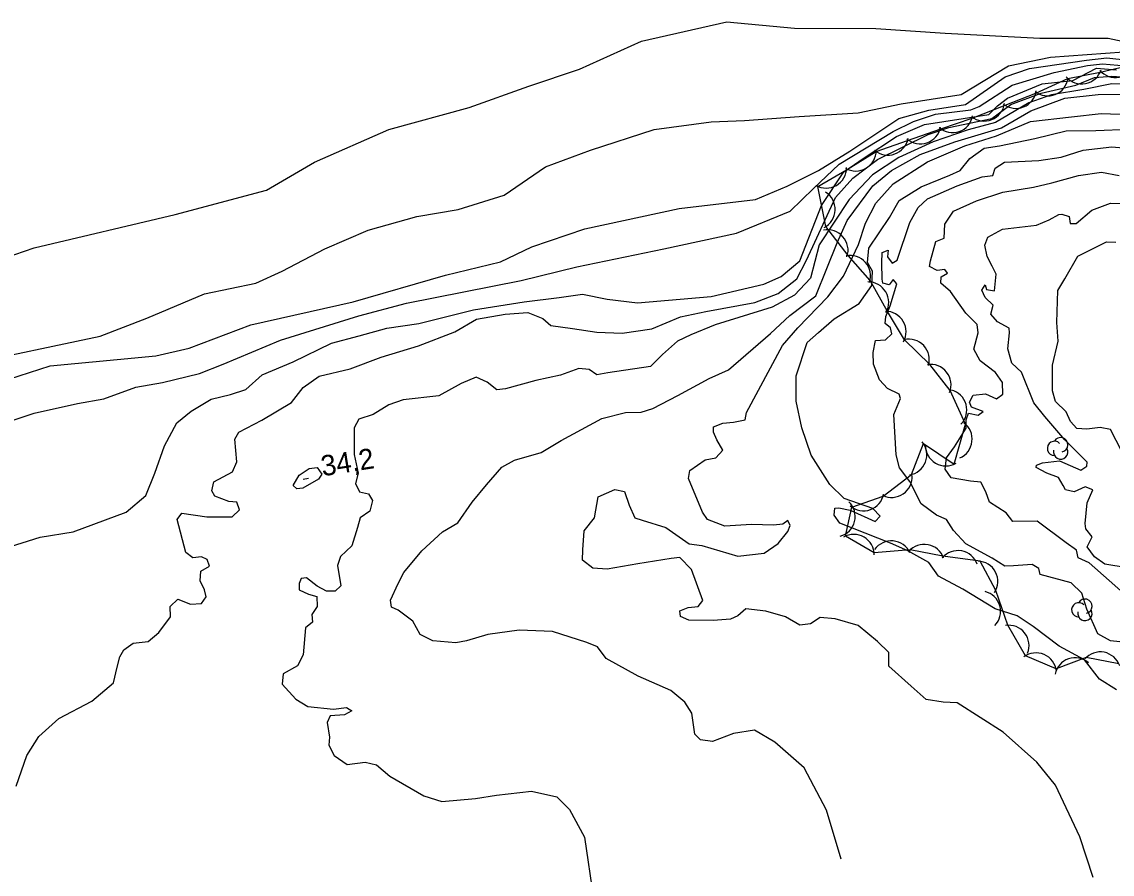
# Model space of a CAD drawing. Extents: x 646142 to 649934, y 5874075 to 5876351.
# Drawn here: x 648669.3 to 648828.8, y 5874823.8 to 5874948.5 of the extents above; entities that cross this region are included whole.
import ezdxf

# ---------------------------------------------------------------- set-up
doc = ezdxf.new("R2010")
doc.units = 0
for name, color, linetype in [('Niveau 1', 7, 'Continuous'), ('Niveau 2', 7, 'Continuous'), ('Niveau 3', 7, 'Continuous'), ('Niveau 44', 7, 'Continuous')]:
    doc.layers.add(name, color=color, linetype=linetype)

msp = doc.modelspace()

# ---------------------------------------------------------------- linework, layer by layer
at = {"layer": 'Niveau 1'}
for points in [[(648664.99, 5874870.88), (648672.04, 5874873.1), (648676.83, 5874873.89), (648684.62, 5874876.77), (648687.46, 5874879.19), (648688.81, 5874882.48), (648690.19, 5874886.47), (648692, 5874889.81), (648694.11, 5874891.56), (648697.04, 5874893.3), (648699.86, 5874893.97), (648702.1, 5874894.7), (648704.51, 5874896.84), (648709.04, 5874898.75), (648714.63, 5874901.49), (648718.69, 5874902.55), (648722.72, 5874903.71), (648727.4, 5874904.37), (648735.41, 5874906.35), (648742.8, 5874907.56), (648747.95, 5874908.16), (648751.37, 5874908.67), (648754.94, 5874907.93), (648759.41, 5874907.4), (648770.2, 5874908.31), (648777.87, 5874910.13), (648780.4, 5874911.24), (648783.14, 5874913.53), (648786.34, 5874921.66), (648789.57, 5874926.56), (648792.57, 5874928.64), (648797.29, 5874931.74), (648801.37, 5874933.49), (648807.06, 5874934.38), (648810.81, 5874934.94), (648812.05, 5874936.24), (648813.54, 5874937.34), (648818.61, 5874939.43), (648823.07, 5874939.95), (648826.56, 5874941.75), (648829.48, 5874941.51)], [(648789.02, 5874875.13), (648788.19, 5874876.3), (648788.29, 5874877.35), (648788.86, 5874877.41), (648790.51, 5874877.03), (648794.16, 5874875.39), (648794.88, 5874876.16), (648793.82, 5874877.3), (648789.62, 5874878.77), (648787.53, 5874880.82), (648784.82, 5874885.11), (648783.43, 5874889.09), (648782.61, 5874893.02), (648782.62, 5874896.7), (648784.22, 5874901.6), (648785.88, 5874903.06), (648788.18, 5874905.05), (648791.81, 5874907.31), (648793.68, 5874909.95), (648793.78, 5874912.03), (648793.04, 5874913.32), (648793.25, 5874915.41), (648796.28, 5874919.9), (648797.7, 5874922.37), (648800.91, 5874924.35), (648805.07, 5874926.1), (648806.61, 5874926.74), (648808, 5874928.51), (648810.12, 5874930.02), (648812.37, 5874930.39), (648817.53, 5874931.45), (648822.11, 5874932.56), (648826.47, 5874932.61), (648826.47, 5874932.61), (648831.27, 5874932.82)], [(648829.46, 5874850.75), (648826.97, 5874852.3), (648824.79, 5874855.15), (648821.1, 5874857.14), (648817.3, 5874860.03), (648814.92, 5874861.59), (648811.7, 5874862.6), (648806.98, 5874865.5), (648803.41, 5874867.38), (648802.02, 5874869.4), (648798.94, 5874871.11), (648796.39, 5874872.2), (648789.02, 5874875.13)]]:
    msp.add_lwpolyline(points, dxfattribs=at)
at = {"layer": 'Niveau 2'}
for points in [[(648649.86, 5874908.14), (648671.16, 5874915.44), (648691.75, 5874920.32), (648705.15, 5874923.91), (648712.14, 5874927.99), (648723.01, 5874932.76), (648734.77, 5874935.99), (648743.5, 5874939.1), (648750.9, 5874941.59), (648759.98, 5874945.68), (648772.47, 5874948.53), (648782.38, 5874947.58), (648794.28, 5874947.57), (648804.39, 5874946.88)], [(648804.39, 5874946.88), (648818.24, 5874946.15), (648828.26, 5874946.15), (648845.02, 5874942.51), (648856.18, 5874939.85), (648884.49, 5874933.12), (648906.85, 5874927.33), (648926.66, 5874923.35), (648935.29, 5874921.33), (648949.8, 5874920.69), (648964.39, 5874919.36), (648976.84, 5874914.53), (648990.17, 5874906.3), (649000.31, 5874901.42), (649016.05, 5874896.28), (649031.58, 5874894.83), (649049.16, 5874893.62), (649079, 5874896.65)], [(648660.88, 5874898.32), (648680.8, 5874902.5), (648687.6, 5874905.16), (648696.04, 5874908.7), (648703.55, 5874910.28), (648707.43, 5874912.01), (648713.68, 5874915.3), (648720, 5874918.02), (648727.11, 5874920.01), (648733.16, 5874921.06), (648739.91, 5874923.13), (648745.93, 5874927.32), (648752.52, 5874929.72), (648761.82, 5874932.78), (648770.2, 5874933.87), (648775.06, 5874934.08), (648783.03, 5874934.66), (648791.7, 5874935.2), (648797.95, 5874936.51), (648806.75, 5874937.88), (648813.69, 5874942.07), (648819.82, 5874943.36), (648830.55, 5874944.14)], [(648667.44, 5874896.2), (648673.5, 5874898.19), (648683.29, 5874899.09), (648688.94, 5874899.63), (648693.81, 5874900.78), (648702.84, 5874904.16), (648717.81, 5874907.53), (648731.31, 5874911.43), (648739.34, 5874913.41), (648743.96, 5874915.58), (648751.68, 5874918.22), (648765.51, 5874921.22), (648776.64, 5874922.52), (648781.29, 5874924.46), (648785.9, 5874926.74), (648790.44, 5874929.59), (648797.65, 5874934.38), (648802.04, 5874935.59), (648807.4, 5874936.44), (648813.19, 5874940.48), (648816.76, 5874941.71), (648825.1, 5874942.91), (648828.08, 5874943.26), (648834.32, 5874942.59)], [(648796.81, 5874932.45), (648799.76, 5874933.95), (648803, 5874935.03), (648808.15, 5874935.62), (648809.37, 5874936.11), (648814.22, 5874939.23), (648820.37, 5874941.1), (648825.24, 5874942.13), (648827.41, 5874942.39), (648830.81, 5874942.09)], [(648689.39, 5874859.16), (648691.09, 5874861.45), (648691.02, 5874862.95), (648692.17, 5874864.01), (648694, 5874863.29), (648695.61, 5874863.37), (648696.3, 5874864.37), (648696.07, 5874865.39), (648695.44, 5874866.71), (648695.51, 5874868.11), (648696.81, 5874868.84), (648696.46, 5874869.84), (648695.61, 5874870.2), (648694.35, 5874870.05), (648693.32, 5874870.86), (648692.05, 5874875.69), (648692.75, 5874876.59), (648696.41, 5874876.09), (648700.12, 5874876.06), (648701.16, 5874877.11), (648700.79, 5874878.22), (648699.62, 5874878.32), (648697.55, 5874879.12), (648697.12, 5874879.88), (648697.42, 5874881.19), (648700.14, 5874882.66), (648700.78, 5874884.13), (648700.5, 5874887.45), (648701.07, 5874888.45), (648704.45, 5874890.23), (648708.78, 5874892.82), (648710.49, 5874894.99), (648712.84, 5874896.65), (648717.35, 5874897.75), (648721.9, 5874899.44), (648721.9, 5874899.44), (648727.37, 5874901.12), (648732.69, 5874903.13), (648735.83, 5874905), (648740.03, 5874905.72), (648743.36, 5874905.99), (648745.55, 5874905.09), (648746.71, 5874904.07), (648749.89, 5874903.63), (648753.43, 5874903.11), (648757.15, 5874902.97), (648761.48, 5874903.59), (648765.67, 5874905.35), (648769.4, 5874906.13), (648776.54, 5874907.43), (648779.96, 5874908.75), (648782.71, 5874910.92), (648784.12, 5874913.63), (648788.34, 5874922.8), (648790.9, 5874925.64), (648794.5, 5874928.37), (648801.93, 5874932.01), (648804.93, 5874933.06), (648811.25, 5874934.37), (648814.01, 5874936.43), (648818.43, 5874938.1), (648823.5, 5874939.26), (648826.25, 5874940.39), (648828.78, 5874940.57), (648835.07, 5874940.15)], [(648832.94, 5874939.35), (648828.77, 5874939.44), (648824.71, 5874938.63), (648819.95, 5874937.84), (648816.63, 5874936.65), (648811.78, 5874933.78), (648807.75, 5874932.73), (648802.65, 5874930.98), (648797.61, 5874928.66), (648793.76, 5874926.14), (648790.38, 5874922.51), (648785.98, 5874915.88), (648784.72, 5874910.99), (648782.36, 5874908.52), (648779.1, 5874906.76), (648770.75, 5874904.17)], [(648789.18, 5874825.98), (648787.05, 5874833.13), (648783.77, 5874839.32), (648779.5, 5874843.1), (648776.52, 5874844.83), (648773.46, 5874844.35), (648770.37, 5874843.18), (648768.6, 5874843.44), (648767.81, 5874844.27), (648767.33, 5874847.33), (648766.32, 5874848.95), (648764.27, 5874850.67), (648759.51, 5874852.77), (648754.82, 5874855.34), (648753.57, 5874857.04), (648751.99, 5874857.66), (648746.95, 5874859.27), (648742.07, 5874859.5), (648737.53, 5874858.86), (648734.4, 5874857.92), (648732.82, 5874857.61), (648729.44, 5874857.91), (648727.59, 5874858.85), (648726.55, 5874860.81), (648724.39, 5874862.4), (648723.41, 5874862.87), (648723.29, 5874863.89), (648724.38, 5874866.33), (648725.23, 5874867.93), (648727.85, 5874871.12), (648730.87, 5874873.9), (648733.14, 5874875.2), (648735.2, 5874878.21), (648737.32, 5874880.77), (648739.56, 5874883.34), (648741.4, 5874884.36), (648745.3, 5874885.51), (648748.21, 5874887.23), (648754.17, 5874890.47), (648757.65, 5874891.33), (648759.95, 5874891.37), (648761.62, 5874891.91), (648765.31, 5874893.84), (648769.86, 5874896.34), (648772.71, 5874897.59), (648778.88, 5874902.92), (648781.68, 5874905.56), (648785.49, 5874908.42), (648787.09, 5874912.41), (648788.6, 5874916.17), (648790.05, 5874919.45), (648793.82, 5874924.5), (648796.55, 5874926.78), (648800.76, 5874929.11), (648805.84, 5874930.97), (648812.63, 5874933.03), (648816.95, 5874935.49), (648821.91, 5874937.33), (648826.8, 5874937.9), (648831.29, 5874937.96)], [(648773.45, 5874889.95), (648775.14, 5874890.26), (648775.14, 5874890.26), (648775.36, 5874891.33), (648780.63, 5874901.16), (648782.86, 5874903.72), (648787.26, 5874908.26), (648789.55, 5874911.29), (648791.75, 5874915.92), (648792.76, 5874919.04), (648794.25, 5874921.97), (648796.79, 5874924.8), (648801.81, 5874928.03), (648807.29, 5874930.39), (648811.94, 5874931.86), (648816.88, 5874933.93), (648822.89, 5874934.63), (648827.21, 5874935.13), (648835.53, 5874934.83)], [(648666.88, 5874889.81), (648671.13, 5874891.23), (648677.47, 5874892.67), (648681.35, 5874893.35), (648686.03, 5874895.06), (648689.9, 5874895.74), (648695.33, 5874897.07), (648698.77, 5874898.4), (648707.19, 5874901.94), (648718.62, 5874905.47), (648725.61, 5874907.33), (648742.4, 5874910.68), (648750.53, 5874912.67), (648763.23, 5874915.31), (648773.87, 5874917.6), (648781.72, 5874920.83), (648785.16, 5874924.13), (648788.91, 5874927.7), (648796.81, 5874932.45)], [(648795.19, 5874914.75), (648796.07, 5874915.08), (648795.95, 5874914.15), (648796.64, 5874913.2), (648797.39, 5874913.63), (648799.25, 5874919.13), (648800.48, 5874921.33), (648801.82, 5874922.64), (648806.18, 5874924.52), (648809.81, 5874925.86), (648811.39, 5874926.05), (648811.72, 5874927.12), (648813.11, 5874927.97), (648818.13, 5874928.21), (648821.4, 5874928.7), (648824.6, 5874929.76), (648828.79, 5874930.25), (648834.35, 5874929.75)], [(648802.12, 5874912.71), (648802.25, 5874913.52), (648803.06, 5874916.37), (648804.26, 5874916.85), (648804.35, 5874918.92), (648805.62, 5874920.79), (648808.98, 5874922.33), (648812.84, 5874923.58), (648817.34, 5874924.33), (648820.01, 5874924.98), (648823.89, 5874926.01), (648827.27, 5874926.52), (648829.85, 5874926.01)], [(648810.66, 5874917.03), (648812.81, 5874918.2), (648817.77, 5874918.77), (648819.62, 5874919.56), (648821.02, 5874920.3), (648821.47, 5874920.35), (648822.54, 5874920.02), (648822.67, 5874919), (648823.58, 5874918.99), (648825.86, 5874920.97), (648828.6, 5874921.98), (648830.09, 5874921.92)], [(648831.04, 5874868.6), (648827.77, 5874869.14), (648826.27, 5874870.22), (648825.17, 5874871.7), (648825.91, 5874873.16), (648824.97, 5874874.31), (648824.88, 5874875.1), (648825.2, 5874878.11), (648826, 5874880.03), (648824.91, 5874880.48), (648823.29, 5874879.72), (648821.99, 5874880.02), (648821.69, 5874880.67), (648820.97, 5874881.85), (648819.3, 5874882.46), (648817.71, 5874883.3), (648817.78, 5874883.65), (648818.65, 5874883.98), (648821.14, 5874884.27), (648824.27, 5874882.92), (648825.12, 5874883.48), (648825.17, 5874884.06), (648821.91, 5874887.34), (648818.98, 5874890.77), (648817.37, 5874892.76), (648815.57, 5874897.24), (648814.15, 5874898.56), (648813.55, 5874900.67), (648813.84, 5874902.99), (648813.76, 5874903.67), (648812.05, 5874904.61), (648811.11, 5874905.76), (648811.41, 5874907.05), (648810.24, 5874908.17), (648809.77, 5874909.26), (648810.25, 5874910.01), (648810.44, 5874909.34), (648811.61, 5874909.14), (648811.89, 5874911.57), (648811.29, 5874912.76), (648810.55, 5874914.16), (648810.23, 5874915.84), (648810.66, 5874917.03)], [(648830.23, 5874885.63), (648828.58, 5874888.87), (648827.06, 5874889.15), (648825.14, 5874888.92), (648823.65, 5874888.98), (648822.73, 5874890.01), (648822.1, 5874891.42), (648820.54, 5874892.96), (648820.13, 5874894.51), (648820.13, 5874898.28), (648820.96, 5874901.8), (648820.75, 5874904.52), (648820.87, 5874909.21), (648821.92, 5874910.93), (648823.8, 5874914.24), (648828, 5874916.32), (648829.38, 5874916.26)], [(648832.75, 5874857.48), (648828.57, 5874857.91), (648826.72, 5874858.96), (648825.14, 5874862.56), (648824.4, 5874864.89), (648822.83, 5874866.43), (648818.32, 5874867.63), (648818.1, 5874868.52), (648817.11, 5874869.09), (648814.38, 5874868.89), (648813.12, 5874868.85), (648811.26, 5874870.02), (648807.45, 5874872.1), (648805.61, 5874874.06), (648804.61, 5874875.67), (648803.15, 5874876.3), (648800.88, 5874877.99), (648799.23, 5874881.24), (648797.72, 5874883.25), (648797.26, 5874885.15), (648796.89, 5874891.07), (648797.88, 5874893.37), (648797.69, 5874894.04), (648795.98, 5874894.87), (648794.8, 5874896.11), (648793.94, 5874898.42), (648793.85, 5874900.13), (648794.21, 5874901.9), (648795.7, 5874901.96), (648796.62, 5874902.87), (648796.4, 5874903.76), (648795.64, 5874904.36), (648795.74, 5874905.4), (648796.36, 5874906.97), (648797.35, 5874910.18), (648796.81, 5874910.81), (648796.22, 5874910.05), (648795.27, 5874910.28), (648795.2, 5874910.85), (648795.14, 5874913.25), (648795.19, 5874914.75)], [(648830.47, 5874864.89), (648825.46, 5874869.35), (648823.88, 5874870.09), (648823.63, 5874871.2), (648822.13, 5874872.29), (648817.85, 5874875.46), (648814.3, 5874875.39), (648813.35, 5874876.65), (648810.87, 5874878.2), (648810.34, 5874879.74), (648809.6, 5874881.14), (648808.09, 5874881.31), (648805.28, 5874881.79), (648804.43, 5874883.06), (648804.58, 5874884.69), (648805.76, 5874886.31), (648807.5, 5874889.04), (648807.46, 5874890.29), (648807.8, 5874891.25), (648809.22, 5874890.96), (648809.95, 5874891.5), (648808.27, 5874892.11), (648807.95, 5874892.87), (648808.52, 5874893.86), (648810.33, 5874894.07), (648811.91, 5874893.33), (648812.86, 5874894.02), (648812.77, 5874895.73), (648811.78, 5874897.22), (648809.52, 5874898.9), (648808.62, 5874900.63), (648809.25, 5874902.99), (648809.1, 5874904.24), (648807.42, 5874905.87), (648805.2, 5874909.05), (648803.79, 5874910.27), (648803.8, 5874911.18), (648804.76, 5874911.75), (648804.35, 5874912.28), (648803.22, 5874912.15), (648802.12, 5874912.71)], [(648770.75, 5874904.17), (648767.22, 5874902.72), (648767.22, 5874902.72), (648765.25, 5874901.79), (648763.06, 5874899.81), (648761.3, 5874898.1), (648755.06, 5874897.14), (648753.47, 5874896.84), (648752.34, 5874897.63), (648750.81, 5874897.8), (648748.16, 5874896.8), (648744.55, 5874896.03), (648740.07, 5874894.81), (648738.81, 5874894.67), (648737.41, 5874895.78), (648735.82, 5874896.52), (648733.62, 5874895.57), (648730.36, 5874893.8), (648725.11, 5874893.19), (648723, 5874892.48), (648720.74, 5874891.06), (648718.62, 5874890.35), (648717.96, 5874889.12), (648717.97, 5874885.19), (648718.53, 5874882.48), (648718.13, 5874880.93), (648718.74, 5874879.73), (648720.05, 5874879.42), (648720.63, 5874878.44), (648720.24, 5874876.89), (648718.85, 5874875.92), (648718.44, 5874874.49), (648717.6, 5874871.85), (648715.94, 5874870.26), (648715.52, 5874868.94), (648715.99, 5874865.99), (648715.16, 5874865.2), (648713.89, 5874865.17), (648712.52, 5874865.93), (648710.99, 5874867.14), (648710.19, 5874867.05), (648709.93, 5874866.32), (648709.92, 5874865.4), (648711.28, 5874864.75), (648712.47, 5874864.42), (648712.54, 5874862.93), (648711.74, 5874861.79), (648711.88, 5874860.65), (648710.82, 5874859.83), (648710.49, 5874855.86), (648709.64, 5874854.26), (648707.58, 5874853.09), (648707.41, 5874851.57), (648709.41, 5874849.37), (648711.16, 5874848.31), (648714.91, 5874847.93), (648716.85, 5874848.16), (648717.6, 5874847.67), (648716.52, 5874847.08), (648714.45, 5874846.95), (648713.99, 5874845.98), (648714.36, 5874843.82), (648714.27, 5874842.65), (648715.03, 5874841.12), (648716.92, 5874839.84)], [(648806.18, 5874848.84), (648804.09, 5874848.94), (648801.62, 5874849.34), (648799.43, 5874851.27), (648796.19, 5874854.24), (648796.18, 5874856.2), (648794.49, 5874857.84), (648791.67, 5874860.16), (648788.33, 5874861.16), (648786.11, 5874861.36), (648784.73, 5874860.39), (648783.14, 5874860.2), (648781.03, 5874861.45), (648778.16, 5874862.27), (648775.24, 5874862.62), (648774.1, 5874861.57), (648773, 5874861.09), (648770.49, 5874860.91), (648766.91, 5874860.96), (648765.69, 5874861.51), (648765.59, 5874862.3), (648766.8, 5874862.79), (648768.28, 5874862.96), (648768.98, 5874863.85), (648767.29, 5874868.38), (648765.58, 5874870.14), (648764.32, 5874869.99), (648759.46, 5874869.19), (648754.94, 5874868.43), (648752.85, 5874868.54), (648751.33, 5874869.74), (648751.38, 5874871.24), (648751.62, 5874874.04), (648753.12, 5874875.94), (648753.67, 5874879), (648756.08, 5874880.09), (648757.5, 5874879.8), (648758.2, 5874877.8), (648759, 5874875.94), (648760.08, 5874875.6), (648763.55, 5874874.51), (648766.95, 5874872.14), (648768.82, 5874871.9), (648774.08, 5874870.32), (648777.95, 5874870.77), (648779.97, 5874872.16), (648781.37, 5874873.94), (648781.73, 5874874.79), (648781.41, 5874875.56), (648780.67, 5874875.01), (648779.3, 5874874.85), (648776.06, 5874874.93), (648772.17, 5874874.71), (648769.63, 5874875.68), (648768.93, 5874876.75), (648766.84, 5874881.69), (648767.04, 5874882.87), (648769.28, 5874884.4), (648770.86, 5874884.7), (648771.87, 5874885.85), (648771, 5874887.36), (648770.52, 5874888.46), (648770.54, 5874889.27), (648771.86, 5874889.77), (648773.45, 5874889.95)], [(648709.89, 5874882.17), (648711.39, 5874883.15), (648712.53, 5874883.29), (648713.22, 5874882.33), (648712.74, 5874881.58), (648710.46, 5874880.27), (648709.55, 5874880.16), (648709.02, 5874880.68), (648709.89, 5874882.17)], [(648668.53, 5874836.67), (648670.08, 5874841.14), (648671.84, 5874843.9), (648674.77, 5874846.56), (648679.57, 5874849.09), (648682.73, 5874851.78), (648683.27, 5874854.05), (648683.67, 5874855.6), (648684.24, 5874856.59), (648685.64, 5874857.57), (648687.81, 5874857.82), (648689.39, 5874859.16)], [(648826.08, 5874823.27), (648824.09, 5874829.26), (648820.53, 5874836.8), (648817.82, 5874840.17), (648812.91, 5874844.55), (648806.18, 5874848.84)], [(648716.92, 5874839.84), (648719.55, 5874840.15), (648721.22, 5874839.76), (648723.15, 5874838.14), (648728.12, 5874835.25), (648730.77, 5874834.4), (648735.69, 5874834.86), (648738.76, 5874835.34), (648743.9, 5874835.94), (648747.59, 5874835.1), (648749.43, 5874833.23), (648751.65, 5874829.21), (648752.96, 5874820.22), (648753.84, 5874810.02), (648753.02, 5874797.54), (648747.53, 5874782.54), (648742.53, 5874772.11), (648739.6, 5874765.62), (648733.51, 5874755.52), (648720.59, 5874732.79), (648717.04, 5874727.62), (648712.01, 5874720.3)]]:
    msp.add_lwpolyline(points, dxfattribs=at)
at = {"layer": 'Niveau 3'}
msp.add_line((648710.49, 5874881.59), (648711.28, 5874881.71), dxfattribs=at)
at = {"layer": 'Niveau 44'}
msp.add_lwpolyline([(648829.82, 5874854.57), (648825.05, 5874855.49), (648820.62, 5874853.82), (648816.16, 5874855.73), (648813.55, 5874860.21), (648811.8, 5874865.28), (648809.54, 5874869.57), (648804.06, 5874870.33), (648799.29, 5874871.22), (648794.01, 5874870.82), (648789.81, 5874873.26), (648790.76, 5874877.47), (648795.34, 5874879.1), (648799.5, 5874882.27), (648801.23, 5874886.8), (648805.72, 5874883.77), (648807.39, 5874889.65), (648805.16, 5874894.58), (648802.15, 5874898.39), (648798.45, 5874901.97), (648795.97, 5874906.14), (648793.42, 5874910.68), (648790.22, 5874914.33), (648786.97, 5874918.57), (648785.78, 5874924.44), (648789.98, 5874926.87), (648794.33, 5874929.56), (648798.91, 5874931.15), (648803.77, 5874932.84), (648808.36, 5874934.44), (648813.16, 5874936.31), (648817.67, 5874938.1), (648822.33, 5874940.25), (648827.1, 5874941.17), (648832.08, 5874942.34)], dxfattribs=at)
for centre, radius, start, end in [((648829.29, 5874943.38), 3, 220.837, 340.815), ((648824.38, 5874942.44), 3, 220.837, 340.815), ((648819.41, 5874940.69), 3, 231.6736, 351.6515), ((648814.77, 5874938.85), 3, 231.6736, 351.6515), ((648810.12, 5874937), 3, 231.6736, 351.6515), ((648805.48, 5874935.31), 3, 229.1939, 349.1719), ((648800.76, 5874933.66), 3, 229.1939, 349.1719), ((648796.04, 5874932.02), 3, 229.1939, 349.1719), ((648791.32, 5874929.69), 3, 240.0978, 0.0758), ((648786.99, 5874927.18), 3, 240.0978, 0.0758), ((648785.31, 5874921.07), 3, 297.6031, 57.5811), ((648787.2, 5874915.1), 3, 341.2027, 101.1806), ((648790.49, 5874911.34), 3, 341.2027, 101.1806), ((648793.15, 5874907.46), 3, 330.6532, 90.6312), ((648795.69, 5874903.15), 3, 330.6532, 90.6312), ((648799.09, 5874899.08), 3, 343.0644, 103.0424), ((648802.27, 5874895.39), 3, 338.3603, 98.3382), ((648804.57, 5874891.72), 3, 315.7323, 75.7102), ((648805.35, 5874887.45), 3, 293.3187, 53.2966), ((648798.72, 5874885.17), 3, 279.0283, 39.0063), ((648804.53, 5874886.52), 3, 179.4447, 299.4226), ((648820.4, 5874886.09), 1.05, 44.1154, 269.804), ((648821.3, 5874886.62), 1.05, 282.2692, 149.7263), ((648821.3, 5874885.57), 1.05, 166.9369, 29.6212), ((648796.6, 5874881.92), 3, 244.0286, 4.0066), ((648792.46, 5874879.95), 3, 229.5524, 349.5303), ((648788.24, 5874876.13), 3, 285.8253, 45.8033), ((648791.03, 5874870.51), 3, 359.8799, 119.8579), ((648796.53, 5874869.55), 3, 24.8988, 144.8768), ((648801.35, 5874869.05), 3, 19.432, 139.4099), ((648806.27, 5874868.13), 3, 19.432, 139.4099), ((648809.11, 5874866.6), 3, 327.7118, 87.6897), ((648809.51, 5874862.23), 3, 316.0396, 76.0175), ((648823.95, 5874862.46), 1.05, 44.1154, 269.804), ((648824.85, 5874862.99), 1.05, 282.2692, 149.7263), ((648824.85, 5874861.94), 1.05, 166.9369, 29.6212), ((648813.68, 5874857.21), 3, 338.4335, 98.4115), ((648827.1, 5874853.3), 3, 19.0553, 139.0332), ((648817.69, 5874853.16), 3, 6.747, 126.725), ((648823.42, 5874852.46), 3, 48.9098, 168.8878)]:
    msp.add_arc(centre, radius, start, end, dxfattribs=at)

# ---------------------------------------------------------------- texts
at = {"layer": 'Niveau 3'}
msp.add_text('34,2 ', height=3, rotation=8.9405, dxfattribs=at).set_placement((648713.34, 5874882))

doc.saveas('drawing.dxf')
